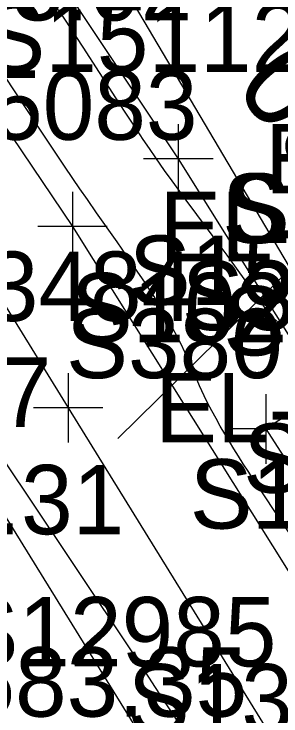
# Model space of a CAD drawing. Extents: x 1729869 to 1735532, y 648588 to 653771.
# Drawn here: x 1731663.72 to 1731679.11, y 651454.2 to 651494.67 of the extents above; entities that cross this region are included whole.
import ezdxf

# ---------------------------------------------------------------- set-up
doc = ezdxf.new("R2010")
doc.units = 0
for name, color, linetype in [('SURVEY - CONTOURS - Index with Text', 7, 'Continuous'), ('SURVEY - CONTOURS - Intermediate with optional Text', 7, 'Continuous'), ('SURVEY - DRAINAGE - Area Shapes Text', 7, 'Continuous'), ('SURVEY - DRAINAGE - Storm Sewer', 7, 'Continuous'), ('SURVEY - DRAINAGE - Storm Sewer - Points - Numbers', 7, 'Continuous'), ('SURVEY - DTM - Breaklines', 7, 'Continuous'), ('SURVEY - DTM - Breaklines - Points - Elevations', 7, 'Continuous'), ('SURVEY - DTM - Breaklines - Points - Locators', 7, 'Continuous'), ('SURVEY - DTM - Breaklines - Points - Numbers', 7, 'Continuous'), ('SURVEY - MISCELLANEOUS - Bottom of MH and CB - Points - Numbers', 7, 'Continuous'), ('SURVEY - NON-TRANSPORTATION - Features - Points - Locators', 7, 'Continuous'), ('SURVEY - NON-TRANSPORTATION - Features - Points - Numbers', 7, 'Continuous'), ('SURVEY - TRAFFIC CONTROL - Pavement Marking - Points - Elevations', 7, 'Continuous'), ('SURVEY - TRANSPORTATION - Features', 7, 'Continuous'), ('SURVEY - TRANSPORTATION - Features - Points - Elevations', 7, 'Continuous'), ('SURVEY - TRANSPORTATION - Features - Points - Locators', 7, 'Continuous'), ('SURVEY - TRANSPORTATION - Features - Points - Numbers', 7, 'Continuous'), ('SURVEY - TRANSPORTATION - Roads', 7, 'Continuous'), ('SURVEY - TRANSPORTATION - Roads - Points - Elevations', 7, 'Continuous'), ('SURVEY - TRANSPORTATION - Roads - Points - Numbers', 7, 'Continuous')]:
    doc.layers.add(name, color=color, linetype=linetype)

msp = doc.modelspace()

# ---------------------------------------------------------------- linework, layer by layer
at = {"layer": 'SURVEY - CONTOURS - Intermediate with optional Text'}
for points in [[(1731666.277, 651494.936), (1731667.688, 651492.76), (1731669.582, 651489.833), (1731670.121, 651489.005), (1731670.458, 651488.49), (1731670.802, 651487.968), (1731671.154, 651487.44), (1731671.514, 651486.907), (1731671.882, 651486.37), (1731672.383, 651485.654), (1731672.818, 651485.045), (1731673.225, 651484.486), (1731673.634, 651483.929), (1731675.472, 651481.455), (1731675.986, 651480.757), (1731676.725, 651479.743), (1731677.369, 651478.849), (1731677.981, 651477.987), (1731678.099, 651477.823), (1731678.213, 651477.671), (1731678.327, 651477.527), (1731678.444, 651477.39), (1731678.569, 651477.255), (1731678.665, 651477.159), (1731678.88, 651476.955), (1731679.135, 651476.718)], [(1731679.98, 651464.164), (1731678.956, 651465.698), (1731677.967, 651467.175), (1731677.492, 651467.893), (1731677.216, 651468.314), (1731676.942, 651468.739), (1731676.669, 651469.167), (1731676.4, 651469.597), (1731676.136, 651470.028), (1731675.872, 651470.469), (1731675.616, 651470.909), (1731675.369, 651471.348), (1731675.131, 651471.786), (1731674.905, 651472.221), (1731674.692, 651472.653), (1731674.553, 651472.947), (1731674.419, 651473.24), (1731674.277, 651473.562), (1731673.86, 651474.53), (1731673.717, 651474.853), (1731673.569, 651475.178), (1731673.353, 651475.627), (1731673.125, 651476.077), (1731672.886, 651476.527), (1731672.637, 651476.975), (1731672.38, 651477.42), (1731672.116, 651477.86), (1731671.955, 651478.12), (1731671.793, 651478.379), (1731671.628, 651478.636), (1731671.294, 651479.146), (1731671.125, 651479.401), (1731670.832, 651479.835), (1731670.538, 651480.267), (1731670.243, 651480.695), (1731669.661, 651481.528), (1731668.474, 651483.213), (1731667.95, 651483.969), (1731667.527, 651484.589), (1731666.681, 651485.842), (1731665.335, 651487.858), (1731662.39, 651492.267)], [(1731673.395, 651453.512), (1731672.951, 651454.208), (1731672.426, 651455.018), (1731671.885, 651455.844), (1731671.103, 651457.023), (1731666.778, 651463.5), (1731663.098, 651469.016)]]:
    msp.add_lwpolyline(points, dxfattribs=at)
at = {"layer": 'SURVEY - DRAINAGE - Area Shapes Text'}
msp.add_line((1731882.052, 651679.427), (1731669.716, 651470.194), dxfattribs=at)
at = {"layer": 'SURVEY - DRAINAGE - Storm Sewer'}
msp.add_line((1731578.313, 651651.699), (1731685.778, 651469.58), dxfattribs=at)
at = {"layer": 'SURVEY - DTM - Breaklines'}
for points in [[(1731329.074, 651966.061), (1731359.729, 651926.546), (1731391.78, 651888.069), (1731423.005, 651848.978), (1731455.159, 651810.576), (1731479.951, 651777.549), (1731506.268, 651734.811), (1731535.375, 651694.144), (1731562.198, 651652.748), (1731588.043, 651609.921), (1731613.605, 651566.913), (1731639.146, 651523.891), (1731667.1, 651482.416), (1731693.639, 651440.035), (1731719.242, 651397.052), (1731747.215, 651355.589), (1731769.127, 651321.344), (1731788.96, 651288.223), (1731795.994, 651292.731)], [(1731576.496, 651649.132), (1731594.653, 651614.159), (1731618.963, 651570.347), (1731645.49, 651527.958), (1731673.195, 651486.323), (1731681.582, 651472.895)], [(1731687.137, 651476.467), (1731678.235, 651470.743), (1731685.143, 651460.001)]]:
    msp.add_lwpolyline(points, dxfattribs=at)
at = {"layer": 'SURVEY - DTM - Breaklines - Points - Locators'}
for p, q in [((1731673.195, 651488.323), (1731673.195, 651484.323)), ((1731675.195, 651486.323), (1731671.195, 651486.323)), ((1731667.1, 651484.416), (1731667.1, 651480.416)), ((1731669.1, 651482.416), (1731665.1, 651482.416)), ((1731678.235, 651472.743), (1731678.235, 651468.743)), ((1731680.235, 651470.743), (1731676.235, 651470.743))]:
    msp.add_line(p, q, dxfattribs=at)
at = {"layer": 'SURVEY - NON-TRANSPORTATION - Features - Points - Locators'}
msp.add_line((1731682.728, 651471.447), (1731678.728, 651471.447), dxfattribs=at)
at = {"layer": 'SURVEY - TRANSPORTATION - Features'}
msp.add_lwpolyline([(1731488.583, 651750.084), (1731505.82, 651725.418), (1731522.61, 651700.555), (1731539.376, 651675.596), (1731555.896, 651650.419), (1731572.103, 651625.11), (1731588.174, 651599.752), (1731603.915, 651574.173), (1731619.68, 651548.614), (1731635.384, 651523.051), (1731651.111, 651497.511), (1731666.851, 651471.969), (1731681.519, 651448.187), (1731693.14, 651429.418), (1731705.36, 651409.566), (1731719.947, 651387.218), (1731733.738, 651366.345), (1731747.606, 651345.527), (1731775.267, 651303.843)], dxfattribs=at)
at = {"layer": 'SURVEY - TRANSPORTATION - Features - Points - Locators'}
for p, q in [((1731666.851, 651473.969), (1731666.851, 651469.969)), ((1731668.851, 651471.969), (1731664.851, 651471.969))]:
    msp.add_line(p, q, dxfattribs=at)
at = {"layer": 'SURVEY - TRANSPORTATION - Roads'}
msp.add_lwpolyline([(1731473.705, 651759.831), (1731495.592, 651728.764), (1731519.308, 651694.098), (1731534.884, 651670.829), (1731544.725, 651655.757), (1731559.893, 651632.22), (1731568.454, 651618.701), (1731583.36, 651594.996), (1731599.207, 651569.522), (1731613.897, 651545.682), (1731624.386, 651528.652), (1731644.321, 651496.299), (1731671.649, 651452.056), (1731687.333, 651426.479), (1731701.999, 651402.626), (1731716.708, 651378.798), (1731725.118, 651365.186), (1731752.422, 651320.929)], dxfattribs=at)

# ---------------------------------------------------------------- texts
at = {"layer": 'SURVEY - CONTOURS - Index with Text'}
msp.add_text('580', height=5, rotation=128.5673, dxfattribs=at).set_placement((1731687.194, 651484.878))
at = {"layer": 'SURVEY - DRAINAGE - Storm Sewer - Points - Numbers'}
msp.add_text('S380', height=4, dxfattribs=at).set_placement((1731666.725, 651473.674))
at = {"layer": 'SURVEY - DTM - Breaklines - Points - Elevations'}
for s, p in [('EL-580.76', (1731678.195, 651484.323)), ('EL-582.34', (1731672.1, 651480.416))]:
    msp.add_text(s, height=4, dxfattribs=at).set_placement(p)
at = {"layer": 'SURVEY - DTM - Breaklines - Points - Numbers'}
for s, p in [('S15112', (1731661.955, 651491.323)), ('S15083', (1731655.86, 651487.416)), ('S10200', (1731675.724, 651481.467)), ('S10201', (1731676.055, 651481.467)), ('S15113', (1731670.342, 651477.895)), ('S10202', (1731666.995, 651475.743)), ('S15090', (1731676.934, 651467.061)), ('S10198', (1731673.856, 651465.001)), ('S10203', (1731673.903, 651465.001))]:
    msp.add_text(s, height=4, dxfattribs=at).set_placement(p)
at = {"layer": 'SURVEY - MISCELLANEOUS - Bottom of MH and CB - Points - Numbers'}
msp.add_text('S20015', height=4, dxfattribs=at).set_placement((1731675.784, 651474.985))
at = {"layer": 'SURVEY - NON-TRANSPORTATION - Features - Points - Numbers'}
msp.add_text('S385', height=4, dxfattribs=at).set_placement((1731673.392, 651476.447))
at = {"layer": 'SURVEY - TRAFFIC CONTROL - Pavement Marking - Points - Elevations'}
for s, p in [('EL-583.27', (1731641.183, 651470.865)), ('EL-583.35', (1731652.483, 651454.158))]:
    msp.add_text(s, height=4, dxfattribs=at).set_placement(p)
at = {"layer": 'SURVEY - TRANSPORTATION - Features - Points - Elevations'}
msp.add_text('EL-582.76', height=4, dxfattribs=at).set_placement((1731671.851, 651469.969))
at = {"layer": 'SURVEY - TRANSPORTATION - Features - Points - Numbers'}
for s, p in [('S13484', (1731655.611, 651476.969)), ('S13485', (1731670.279, 651453.187))]:
    msp.add_text(s, height=4, dxfattribs=at).set_placement(p)
at = {"layer": 'SURVEY - TRANSPORTATION - Roads - Points - Elevations'}
for s, p in [('EL-583.02', (1731649.321, 651494.299)), ('EL-583.31', (1731645.397, 651464.674))]:
    msp.add_text(s, height=4, dxfattribs=at).set_placement(p)
at = {"layer": 'SURVEY - TRANSPORTATION - Roads - Points - Numbers'}
msp.add_text('S12985', height=4, dxfattribs=at).set_placement((1731660.409, 651457.056))

doc.saveas('drawing.dxf')
